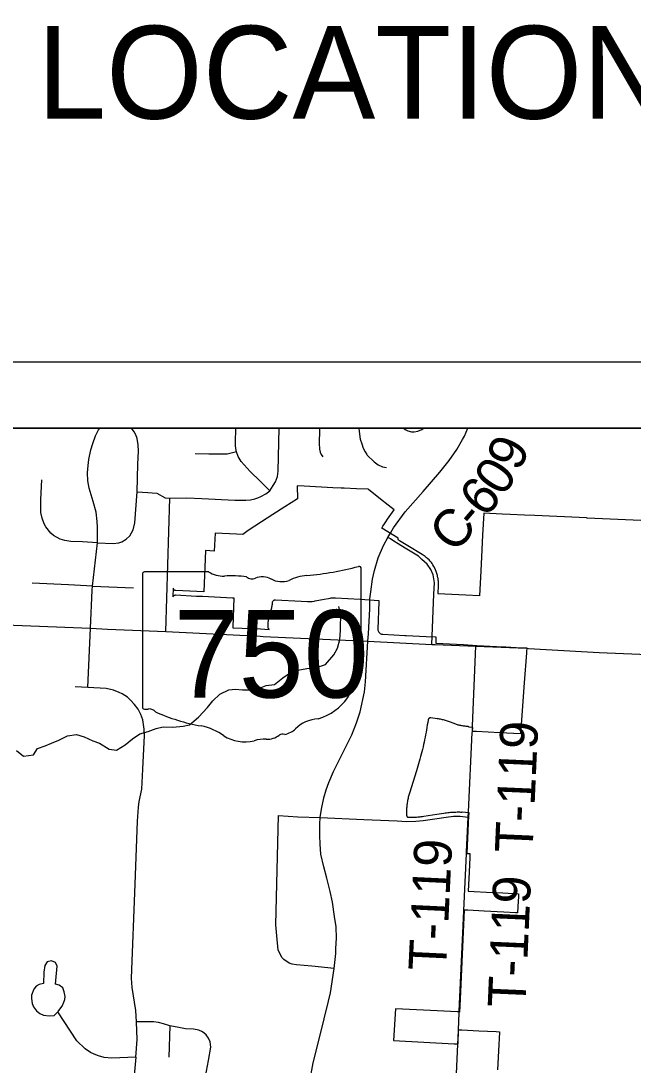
# Model space of a CAD drawing. Extents: x 0 to 34, y 0 to 22.
# Drawn here: x 14.723 to 15.645, y 9.224 to 10.798 of the extents above; entities that cross this region are included whole.
import ezdxf

# ---------------------------------------------------------------- set-up
doc = ezdxf.new("R2010")
doc.units = 0
for name, color, linetype in [('Default', 7, 'Continuous'), ('GM_X_Corporation', 7, 'Continuous'), ('GM_X_County_Road', 7, 'Continuous'), ('GM_X_County_Road_Text', 7, 'Continuous'), ('GM_X_Minor_River', 7, 'Continuous'), ('GM_X_State_Location', 7, 'Continuous'), ('GM_X_State_Route', 7, 'Continuous'), ('GM_X_State_Shield', 7, 'Continuous'), ('GM_X_Township_Road', 7, 'Continuous'), ('GM_X_Township_Road_Text', 7, 'Continuous'), ('SH_Data', 7, 'Continuous')]:
    doc.layers.add(name, color=color, linetype=linetype)

msp = doc.modelspace()

# ---------------------------------------------------------------- linework, layer by layer
at = {"layer": 'GM_X_Corporation'}
for points in [[(19.5646, 10.1841), (12.7646, 10.1841), (12.7646, 8.6719), (12.7953, 8.6676), (12.8119, 8.6756), (12.8296, 8.6783), (12.8448, 8.6761), (12.8988, 8.6726), (13.0467, 8.6615), (13.1161, 8.6564), (13.1948, 8.6507), (13.3525, 8.6386), (13.4613, 8.6292), (13.7169, 8.6042), (13.795, 8.6047), (14.2608, 8.5815), (14.4977, 8.5718), (14.6084, 8.5661), (14.9063, 8.5471), (15.334, 8.5309), (15.3473, 8.5302), (16.0546, 8.4904)], [(17.9872, 10.1841), (13.2832, 10.1841)], [(15.6572, 10.0447), (15.5762, 10.0485), (15.5753, 10.0486), (15.4974, 10.0522), (15.4819, 10.0529), (15.46, 10.054), (15.4479, 10.0545), (15.4203, 10.0559), (15.4186, 10.0226), (15.4168, 9.9902), (15.4157, 9.9689), (15.4137, 9.9314), (15.3935, 9.9322), (15.3513, 9.9341), (15.3514, 9.9349), (15.352, 9.9469), (15.3521, 9.9503), (15.3521, 9.9505), (15.352, 9.9518), (15.3519, 9.9533), (15.3518, 9.9546), (15.3515, 9.9572), (15.3513, 9.9585), (15.3508, 9.9608), (15.3505, 9.9619), (15.3501, 9.9635), (15.3497, 9.9649), (15.3487, 9.9678), (15.3477, 9.9702), (15.347, 9.972), (15.3453, 9.9752), (15.3437, 9.9778), (15.3425, 9.9797), (15.3413, 9.9812), (15.3396, 9.9834), (15.3379, 9.9853), (15.3362, 9.9871), (15.3359, 9.987), (15.3355, 9.9874), (15.3341, 9.9887), (15.3322, 9.9903), (15.3307, 9.9915), (15.329, 9.9926), (15.3274, 9.9937), (15.325, 9.9951), (15.3085, 10.005), (15.2932, 10.0142), (15.2928, 10.0145), (15.2924, 10.0149), (15.292, 10.0153), (15.2918, 10.0157), (15.2915, 10.0163), (15.2914, 10.017), (15.2913, 10.0178), (15.2913, 10.0179), (15.2914, 10.0183), (15.2666, 10.0332), (15.2682, 10.036), (15.2706, 10.0398), (15.2726, 10.0429), (15.2753, 10.0469), (15.2777, 10.0503), (15.2801, 10.0538), (15.2827, 10.0572), (15.2851, 10.0606), (15.2716, 10.0713), (15.2711, 10.0717), (15.2695, 10.073), (15.2468, 10.0915), (15.2463, 10.0919), (15.2286, 10.0926), (15.2101, 10.0933), (15.2087, 10.0934), (15.2052, 10.0935), (15.1927, 10.0942), (15.1497, 10.0965), (15.1392, 10.0971), (15.1395, 10.0774), (15.1206, 10.0654), (15.1025, 10.0537), (15.0852, 10.0425), (15.0655, 10.0298), (15.0573, 10.0238), (15.0477, 10.0243), (15.0153, 10.0258), (15.014, 9.9986), (15.0011, 9.9993), (14.9983, 9.937), (14.956, 9.939), (14.9557, 9.939), (14.9554, 9.9391), (14.9551, 9.9391), (14.9547, 9.9393), (14.9544, 9.9394), (14.9542, 9.9396), (14.9539, 9.9397), (14.9536, 9.94), (14.9534, 9.9402), (14.9532, 9.9404), (14.953, 9.9407), (14.9529, 9.941), (14.9527, 9.9413), (14.9526, 9.9416), (14.9525, 9.9419), (14.9525, 9.9422), (14.9524, 9.9426), (14.9524, 9.9429), (14.9519, 9.9298), (14.9522, 9.93), (14.9524, 9.9306), (14.9528, 9.9311), (14.953, 9.9314), (14.9535, 9.9317), (14.954, 9.9321), (14.9545, 9.9323), (14.9551, 9.9324), (14.9557, 9.9325), (14.9876, 9.9309), (14.9963, 9.9305), (15.0418, 9.9282), (15.0437, 9.9281), (15.0421, 9.8839), (15.0421, 9.883), (15.0837, 9.8812), (15.0971, 9.8806), (15.0967, 9.8809), (15.0964, 9.8812), (15.0962, 9.8815), (15.0959, 9.8819), (15.0957, 9.8822), (15.0956, 9.8826), (15.0955, 9.883), (15.0954, 9.8836), (15.0954, 9.884), (15.0956, 9.8889), (15.0958, 9.8955), (15.0959, 9.8975), (15.0962, 9.8987), (15.0966, 9.9003), (15.1008, 9.9133), (15.1011, 9.9146), (15.1014, 9.9159), (15.1016, 9.9172), (15.1017, 9.9185), (15.1018, 9.921), (15.1019, 9.9217), (15.102, 9.9221), (15.1023, 9.9228), (15.1027, 9.9234), (15.1032, 9.9239), (15.1036, 9.9242), (15.104, 9.9244), (15.1046, 9.9247), (15.1051, 9.9249), (15.1055, 9.925), (15.1062, 9.9251), (15.1453, 9.9231), (15.1548, 9.9227), (15.1566, 9.9226), (15.1592, 9.9226), (15.1619, 9.9228), (15.1646, 9.9231), (15.1663, 9.9234), (15.1797, 9.9261), (15.1864, 9.9274), (15.1887, 9.9278), (15.1902, 9.928), (15.1918, 9.9281), (15.1933, 9.9282), (15.1948, 9.9282), (15.1971, 9.9282), (15.234, 9.9264), (15.2624, 9.9243), (15.2623, 9.922), (15.2608, 9.881), (15.2608, 9.8801), (15.2608, 9.8795), (15.2611, 9.8784), (15.2615, 9.8774), (15.262, 9.8766), (15.2626, 9.8758), (15.2631, 9.8753), (15.2635, 9.8749), (15.264, 9.8746), (15.2643, 9.8744), (15.2653, 9.8738), (15.266, 9.8736), (15.2667, 9.8734), (15.2675, 9.8732), (15.268, 9.8732), (15.3012, 9.8716), (15.3033, 9.8715), (15.3334, 9.8701), (15.3483, 9.8694), (15.3483, 9.8694), (15.3483, 9.8688), (15.3481, 9.8654), (15.3479, 9.8605), (15.3479, 9.8598), (15.3897, 9.8578), (15.4099, 9.8565), (15.4497, 9.8544), (15.4534, 9.8542), (15.469, 9.8535), (15.485, 9.8528), (15.485, 9.8522), (15.4846, 9.8471), (15.4845, 9.8452), (15.4812, 9.8002), (15.4755, 9.7233), (15.4447, 9.7248), (15.4092, 9.7265), (15.4069, 9.7267), (15.4035, 9.7268), (15.4038, 9.7329), (15.3981, 9.7333), (15.3978, 9.7335), (15.3974, 9.7337), (15.397, 9.7339), (15.3966, 9.734), (15.3962, 9.7341), (15.3958, 9.7342), (15.3954, 9.7343), (15.395, 9.7343), (15.3936, 9.7344), (15.3923, 9.7345), (15.391, 9.7346), (15.3897, 9.7348), (15.3884, 9.735), (15.387, 9.7352), (15.3857, 9.7355), (15.3844, 9.7358), (15.3831, 9.7361), (15.3819, 9.7364), (15.3806, 9.7368), (15.3793, 9.7372), (15.3781, 9.7376), (15.3768, 9.7381), (15.3756, 9.7386), (15.3743, 9.7391), (15.3729, 9.7397), (15.3715, 9.7403), (15.37, 9.7408), (15.3686, 9.7413), (15.3671, 9.7418), (15.3656, 9.7423), (15.3642, 9.7428), (15.3627, 9.7432), (15.3612, 9.7436), (15.3597, 9.744), (15.3582, 9.7443), (15.3566, 9.7447), (15.355, 9.745), (15.3535, 9.7452), (15.3519, 9.7455), (15.3503, 9.7457), (15.3405, 9.747), (15.3401, 9.7471), (15.3398, 9.7471), (15.3395, 9.747), (15.3392, 9.747), (15.3389, 9.7469), (15.3386, 9.7468), (15.3383, 9.7467), (15.338, 9.7465), (15.3377, 9.7463), (15.3375, 9.7461), (15.3373, 9.7459), (15.3371, 9.7456), (15.3369, 9.7454), (15.3367, 9.7451), (15.3366, 9.7448), (15.3365, 9.7445), (15.3364, 9.7442), (15.3363, 9.7439), (15.3358, 9.7402), (15.3352, 9.7365), (15.3346, 9.7328), (15.334, 9.7291), (15.3333, 9.7254), (15.3326, 9.7217), (15.3319, 9.718), (15.3312, 9.7143), (15.3304, 9.7106), (15.3296, 9.707), (15.3288, 9.7033), (15.3279, 9.6996), (15.327, 9.696), (15.3261, 9.6924), (15.3251, 9.6887), (15.3242, 9.6851), (15.3232, 9.6815), (15.3221, 9.6779), (15.3211, 9.6743), (15.32, 9.6707), (15.3189, 9.6671), (15.3083, 9.6337), (15.3078, 9.6321), (15.3074, 9.6305), (15.3069, 9.629), (15.3065, 9.6274), (15.3062, 9.6258), (15.3058, 9.6241), (15.3055, 9.6225), (15.3052, 9.6209), (15.305, 9.6193), (15.3048, 9.6177), (15.3046, 9.616), (15.3044, 9.6144), (15.3043, 9.6128), (15.3041, 9.6111), (15.3041, 9.6095), (15.3038, 9.6019), (15.3038, 9.6015), (15.3038, 9.6006), (15.3039, 9.6002), (15.304, 9.5998), (15.3042, 9.5994), (15.3043, 9.599), (15.3045, 9.5986), (15.3047, 9.5983), (15.3049, 9.5979), (15.3052, 9.5976), (15.3059, 9.5975), (15.3067, 9.5975), (15.3077, 9.5975), (15.308, 9.5975), (15.3098, 9.5974), (15.3116, 9.5974), (15.3135, 9.5975), (15.3153, 9.5975), (15.3171, 9.5976), (15.319, 9.5977), (15.3208, 9.5978), (15.3226, 9.598), (15.3244, 9.5982), (15.3262, 9.5984), (15.3281, 9.5986), (15.3299, 9.5989), (15.3497, 9.602), (15.3602, 9.6036), (15.3622, 9.6039), (15.3641, 9.6042), (15.3661, 9.6044), (15.3681, 9.6046), (15.3701, 9.6048), (15.3721, 9.605), (15.3741, 9.6051), (15.3761, 9.6052), (15.3781, 9.6052), (15.38, 9.6053), (15.382, 9.6053), (15.3835, 9.6053), (15.385, 9.6052), (15.3866, 9.6052), (15.3871, 9.6052), (15.3875, 9.6052), (15.3878, 9.6053), (15.3976, 9.6047), (15.3969, 9.591), (15.3968, 9.5885), (15.3948, 9.5428), (15.3983, 9.5426), (15.3995, 9.5426), (15.3993, 9.5374), (15.3982, 9.5144), (15.3969, 9.4861), (15.4336, 9.4841), (15.4489, 9.4833), (15.4726, 9.482), (15.4724, 9.4781), (15.4718, 9.4629), (15.4713, 9.4534), (15.4681, 9.4535), (15.4505, 9.4544), (15.4209, 9.4559), (15.3962, 9.4572), (15.3956, 9.4572), (15.3909, 9.4574), (15.3905, 9.4466), (15.3846, 9.3233), (15.3837, 9.3037), (15.3815, 9.3038), (15.3801, 9.3039), (15.34, 9.306), (15.2873, 9.3087), (15.2844, 9.2606), (15.3758, 9.2558), (15.3779, 9.2557), (15.3817, 9.2555), (15.3824, 9.2769), (15.3875, 9.2767), (15.4127, 9.2755), (15.4388, 9.2742), (15.4438, 9.274), (15.4438, 9.2733), (15.4425, 9.245), (15.4421, 9.2357), (15.4412, 9.2168)]]:
    msp.add_lwpolyline(points, dxfattribs=at)
at = {"layer": 'GM_X_County_Road'}
for p, q in [((15.3913, 10.1717), (15.3963, 10.1841)), ((15.2488, 9.9266), (15.2502, 9.9373))]:
    msp.add_line(p, q, dxfattribs=at)
for points in [[(15.2801, 10.0267), (15.2842, 10.0336), (15.3017, 10.058), (15.329, 10.0887), (15.3539, 10.1175), (15.3684, 10.1354), (15.3799, 10.1518), (15.3885, 10.167), (15.3913, 10.1717)], [(15.2502, 9.9373), (15.2527, 9.9565), (15.2556, 9.9695), (15.261, 9.9883), (15.2694, 10.0069), (15.2756, 10.019), (15.2801, 10.0267)], [(15.2454, 9.8626), (15.2467, 9.8739), (15.2485, 9.9117), (15.2486, 9.9255), (15.2488, 9.9266)], [(15.1737, 9.5569), (15.1731, 9.5699), (15.1732, 9.587), (15.1739, 9.5969), (15.1757, 9.6094), (15.1793, 9.6264), (15.183, 9.6388), (15.1869, 9.6497), (15.1941, 9.6665), (15.2129, 9.7047), (15.2213, 9.7218), (15.2284, 9.7399), (15.2339, 9.7565), (15.2404, 9.7864), (15.2421, 9.8013), (15.2454, 9.8626)], [(15.1976, 9.3994), (15.1982, 9.4149), (15.1979, 9.4323), (15.1956, 9.4478), (15.1921, 9.4695), (15.1889, 9.4856), (15.184, 9.5053), (15.1795, 9.5224), (15.1748, 9.5418), (15.1737, 9.5569)], [(15.1864, 9.3203), (15.1895, 9.3327), (15.1948, 9.3695), (15.1972, 9.3917), (15.1976, 9.3994)], [(15.1574, 9.1952), (15.1576, 9.1972), (15.1633, 9.2272), (15.1732, 9.2668), (15.1864, 9.3203)]]:
    msp.add_lwpolyline(points, dxfattribs=at)
at = {"layer": 'GM_X_Minor_River'}
msp.add_lwpolyline([(14.7159, 9.698), (14.7265, 9.6893), (14.7416, 9.6915), (14.7477, 9.701), (14.7591, 9.7052), (14.7689, 9.7093), (14.7799, 9.7135), (14.7931, 9.72), (14.8064, 9.7222), (14.8181, 9.7184), (14.8313, 9.7124), (14.8412, 9.7089), (14.8559, 9.6998), (14.8669, 9.6983), (14.8798, 9.7067), (14.8911, 9.7154), (14.9021, 9.723), (14.9146, 9.7267), (14.9267, 9.7313), (14.9373, 9.7336), (14.9517, 9.7332), (14.9672, 9.7347), (14.977, 9.7366), (14.9903, 9.748), (15.0039, 9.7628), (15.0118, 9.773), (15.0224, 9.7829), (15.036, 9.7897), (15.0463, 9.7904), (15.0565, 9.7893), (15.0678, 9.7893), (15.0796, 9.7908), (15.0924, 9.7961), (15.1049, 9.7976), (15.1174, 9.8075), (15.1291, 9.8158), (15.1401, 9.8192), (15.1537, 9.8215), (15.167, 9.8226), (15.1817, 9.8276), (15.1942, 9.842), (15.1999, 9.8522), (15.2033, 9.8651), (15.2044, 9.8788), (15.2044, 9.8905), (15.2055, 9.9004), (15.2021, 9.9152)], dxfattribs=at)
at = {"layer": 'GM_X_State_Route'}
for p, q in [((15.088, 9.87), (15.2454, 9.8626)), ((15.2454, 9.8626), (15.3418, 9.858))]:
    msp.add_line(p, q, dxfattribs=at)
for points in [[(14.4741, 9.8907), (14.4887, 9.8946), (14.509, 9.8957), (14.5425, 9.8941), (14.583, 9.892), (14.8278, 9.8824), (14.8534, 9.8809), (14.9413, 9.8772), (15.0831, 9.8702), (15.088, 9.87)], [(15.3418, 9.858), (15.3471, 9.8579), (15.4085, 9.8553), (15.4846, 9.8522), (15.4875, 9.852)], [(15.4875, 9.852), (15.5941, 9.8457), (15.8025, 9.8371), (15.8597, 9.8344), (15.8637, 9.8342), (15.9626, 9.8287), (16.04, 9.8268), (16.0564, 9.8264), (16.1062, 9.8233)]]:
    msp.add_lwpolyline(points, dxfattribs=at)
at = {"layer": 'GM_X_State_Shield'}
for p, q in [((15.0058, 9.9673), (14.9092, 9.9673)), ((15.2356, 9.8675), (15.2356, 9.9722)), ((14.906, 9.9638), (14.906, 9.7637)), ((15.2355, 9.8676), (15.2356, 9.8675))]:
    msp.add_line(p, q, dxfattribs=at)
for centre, major_axis, start_param, end_param in [((14.9098, 9.9642), (0.00382, 0), 1.712693, 3.28349), ((15.0287, 9.9905), (0.037, 0), 4.042523, 4.731795), ((15.1182, 10.2401), (0.3495, 0), 4.814394, 5.042369), ((15.2319, 9.9726), (0.00367, 0), 6.141152, 7.989035), ((15.041, 9.8549), (0.133, 0), 1.404758, 1.657858), ((15.0712, 9.9653), (0.0107, 0), 3.836095, 5.185415), ((15.0869, 9.9421), (0.0222, 0), 0.950623, 2.079405), ((15.1156, 9.9739), (0.0267, 0), 4.081561, 5.145723), ((15.1628, 9.9061), (0.0703, 0), 1.699011, 2.107814), ((15.2347, 9.8598), (0.00568, 0), 1.883978, 3.671073), ((15.1986, 9.8466), (0.0341, 0), 5.934695, 6.695948), ((15.2317, 9.8671), (0.00393, 0), 5.05454, 6.418171), ((15.2487, 9.8237), (0.0248, 0), 2.387724, 3.262537), ((15.1378, 9.8104), (0.0874, 0), 5.101752, 6.440018), ((14.9098, 9.7633), (0.00385, 0), 3.00124, 4.508301), ((14.9104, 9.7837), (0.0294, 0), 4.665946, 4.897461), ((14.9164, 9.7521), (0.0106, 0), 0.519207, 1.627899), ((15.0502, 9.9319), (0.2524, 0), 4.195997, 4.488961), ((15.1746, 9.7075), (0.0479, 0), 1.647645, 2.488434), ((14.975, 9.6738), (0.079, 0), 0.823519, 1.323587), ((15.114, 9.7443), (0.0282, 0), 4.937069, 5.64225), ((15.0604, 9.7512), (0.0501, 0), 4.026481, 4.996735), ((15.0893, 9.682), (0.0412, 0), 1.495662, 1.94098), ((15.093, 9.7362), (0.0267, 0), 4.691044, 5.507374), ((15.1172, 9.7168), (0.00752, 0), 1.147584, 2.315152)]:
    msp.add_ellipse(centre, major_axis=major_axis, ratio=0.8, start_param=start_param, end_param=end_param, dxfattribs=at)
at = {"layer": 'GM_X_Township_Road'}
for p, q in [((14.9413, 9.8772), (14.947, 10.0786)), ((14.8305, 9.9456), (14.8927, 9.9432)), ((14.8236, 9.7928), (14.8278, 9.8824)), ((15.4035, 9.7352), (15.4085, 9.8553)), ((15.3972, 9.6053), (15.403, 9.7252)), ((15.3833, 9.3051), (15.3898, 9.4449)), ((14.9474, 9.283), (14.9458, 9.2355)), ((15.3812, 9.2548), (15.3816, 9.2651))]:
    msp.add_line(p, q, dxfattribs=at)
for points in [[(14.8305, 9.9456), (14.8383, 10.0111), (14.8381, 10.0346), (14.8375, 10.0433), (14.836, 10.0575), (14.8318, 10.0732), (14.8258, 10.0933), (14.8237, 10.1048), (14.823, 10.1167), (14.8241, 10.1279), (14.8251, 10.1369), (14.828, 10.1512), (14.831, 10.1607), (14.8353, 10.1724), (14.8399, 10.1812), (14.8416, 10.1841)], [(14.8383, 10.0111), (14.8616, 10.0101), (14.8705, 10.011), (14.8749, 10.0127), (14.8816, 10.0166), (14.8869, 10.0216), (14.8922, 10.0305), (14.8944, 10.041), (14.8979, 10.0879), (14.8989, 10.1295), (14.8998, 10.1495), (14.8996, 10.1588), (14.8979, 10.1686), (14.896, 10.174), (14.8934, 10.1783), (14.8893, 10.1841)], [(14.8979, 10.0879), (14.9142, 10.0872), (14.9208, 10.0867), (14.9278, 10.0858), (14.9404, 10.079), (14.947, 10.0786), (14.9727, 10.0788), (14.9956, 10.0779), (15.0453, 10.0755), (15.0616, 10.0752), (15.0686, 10.0758), (15.0752, 10.0773), (15.0797, 10.0788), (15.0844, 10.0808), (15.0918, 10.0851), (15.0977, 10.0895), (15.1031, 10.0975), (15.1062, 10.1031), (15.1093, 10.1109), (15.1107, 10.119), (15.1122, 10.1841)], [(15.0977, 10.0895), (15.0833, 10.1039), (15.0685, 10.1186), (15.0545, 10.1336), (15.0504, 10.1414), (15.0479, 10.1483), (15.0469, 10.1534), (15.0464, 10.1578), (15.0464, 10.1616), (15.0467, 10.1841)], [(15.1729, 10.1841), (15.1728, 10.1807), (15.1721, 10.1611), (15.1727, 10.1522), (15.1738, 10.1477), (15.1753, 10.1441), (15.178, 10.1405)], [(15.2322, 10.1841), (15.2324, 10.1787), (15.2341, 10.1676), (15.2363, 10.1605), (15.2386, 10.1538), (15.2415, 10.1482), (15.2439, 10.1442), (15.2448, 10.1431), (15.2549, 10.1332), (15.2612, 10.1286), (15.2679, 10.1259), (15.2735, 10.1246)], [(15.2992, 10.1841), (15.3021, 10.1817), (15.306, 10.1799), (15.3113, 10.1785), (15.3154, 10.1784), (15.321, 10.1796), (15.3271, 10.1817), (15.3302, 10.1841)], [(15.0479, 10.1483), (15.0337, 10.1447), (15.0265, 10.1446), (15.0176, 10.1447), (15.0061, 10.1449), (14.9854, 10.1454)], [(14.8383, 10.0111), (14.8157, 10.0126), (14.7979, 10.0131), (14.7892, 10.0146), (14.7821, 10.0165), (14.772, 10.0221), (14.768, 10.0258), (14.7604, 10.035), (14.758, 10.0395), (14.7546, 10.0483), (14.7527, 10.0566), (14.7529, 10.0766), (14.7541, 10.106)], [(15.2846, 10.0138), (15.2797, 10.0169), (15.2756, 10.019)], [(15.3271, 9.9859), (15.3217, 9.9908), (15.3117, 9.9972), (15.302, 10.0029), (15.2911, 10.0098), (15.2846, 10.0138)], [(15.3418, 9.858), (15.3452, 9.9338), (15.3459, 9.9508), (15.3438, 9.9627), (15.3403, 9.9709), (15.3349, 9.9789), (15.3271, 9.9859)], [(14.8305, 9.9456), (14.7944, 9.9479), (14.7399, 9.9502)], [(14.8278, 9.8824), (14.8302, 9.9396), (14.8305, 9.9456)], [(14.8949, 9.4967), (14.8986, 9.5913), (14.8998, 9.6126), (14.9009, 9.6212), (14.9049, 9.6396), (14.9067, 9.6696), (14.9088, 9.7208), (14.9087, 9.7302), (14.9064, 9.7442), (14.9036, 9.7522), (14.8995, 9.7601), (14.8942, 9.7675), (14.8881, 9.774), (14.8832, 9.7782), (14.8752, 9.7833), (14.871, 9.7854), (14.8622, 9.7888), (14.8513, 9.7914), (14.8236, 9.7928), (14.8046, 9.7938)], [(15.403, 9.7252), (15.4031, 9.7262), (15.4035, 9.7352)], [(15.3944, 9.5452), (15.3968, 9.5973), (15.3972, 9.6053)], [(15.1948, 9.3695), (15.1613, 9.3726), (15.1379, 9.375), (15.1314, 9.3759), (15.1269, 9.3775), (15.1188, 9.3827), (15.1164, 9.3856), (15.1106, 9.397), (15.1087, 9.4184), (15.1068, 9.4354), (15.1108, 9.5999)], [(15.1108, 9.5999), (15.14, 9.5979), (15.1739, 9.5969), (15.2396, 9.594), (15.2896, 9.5919), (15.3041, 9.5912), (15.3181, 9.5913), (15.329, 9.5923), (15.3467, 9.5951), (15.3637, 9.5977), (15.3748, 9.5988), (15.3814, 9.599), (15.3848, 9.599), (15.3968, 9.5973)], [(15.3898, 9.4449), (15.3904, 9.4568), (15.3943, 9.5422), (15.3944, 9.5452)], [(14.8961, 9.2358), (14.8979, 9.2623), (14.8972, 9.289), (14.8961, 9.3062), (14.8903, 9.3408), (14.8894, 9.3547), (14.8949, 9.4967)], [(14.8961, 9.2358), (14.8596, 9.2341), (14.848, 9.2351), (14.8396, 9.2375), (14.8332, 9.24), (14.8276, 9.2429), (14.8198, 9.2482), (14.8072, 9.2601), (14.7784, 9.3038), (14.785, 9.3127), (14.7876, 9.3184), (14.7889, 9.3224), (14.7893, 9.3273), (14.7882, 9.3343), (14.786, 9.3401), (14.7805, 9.3441), (14.7751, 9.3457), (14.7752, 9.3513), (14.7776, 9.3728), (14.7751, 9.3786), (14.7689, 9.381), (14.7623, 9.3792), (14.7589, 9.374), (14.7573, 9.3637), (14.7567, 9.3467), (14.7503, 9.3451), (14.7457, 9.3425), (14.7424, 9.338), (14.7387, 9.3292), (14.7386, 9.3239), (14.7395, 9.3164), (14.742, 9.3117), (14.7464, 9.3057), (14.7515, 9.3016), (14.757, 9.2989), (14.7655, 9.2981), (14.7727, 9.2983), (14.7776, 9.3031)], [(15.3816, 9.2651), (15.382, 9.2763), (15.3832, 9.3031), (15.3833, 9.3051)], [(14.9996, 9.1984), (15.0056, 9.2304), (15.009, 9.2509), (15.0078, 9.2589), (15.0054, 9.2644), (15.0018, 9.2693), (14.9963, 9.2739), (14.9909, 9.2766), (14.983, 9.2781), (14.9706, 9.2785), (14.961, 9.2803), (14.9474, 9.283), (14.9377, 9.2859), (14.9303, 9.2877), (14.9228, 9.2889), (14.9137, 9.2891), (14.8972, 9.289)], [(15.3745, 9.1149), (15.3787, 9.2001), (15.3812, 9.2548)], [(14.8961, 9.2358), (14.8933, 9.2082)]]:
    msp.add_lwpolyline(points, dxfattribs=at)
at = {"layer": 'SH_Data'}
for p, q in [((12.6646, 10.2841), (19.6646, 10.2841)), ((12.7646, 10.1841), (19.5646, 10.1841))]:
    msp.add_line(p, q, dxfattribs=at)

# ---------------------------------------------------------------- texts
at = {"layer": 'Default'}
msp.add_text('LOCATION 5 (FRA-270-20.79)', height=0.14, dxfattribs=at).set_placement((14.7471, 10.6505))
at = {"layer": 'GM_X_County_Road_Text'}
for s, rotation, p in [('9', 65.446, (15.4737, 10.1171)), ('0', 55.889, (15.449, 10.0791)), ('6', 49.9863, (15.4226, 10.0472)), ('C', 49.4048, (15.3767, 9.9935)), ('-', 49.5087, (15.4071, 10.029))]:
    msp.add_text(s, height=0.0568, rotation=rotation, dxfattribs=at).set_placement(p)
at = {"layer": 'GM_X_State_Location'}
for s in ['s', 'r']:
    msp.add_text(s, height=0.000189, dxfattribs=at).set_placement((15.0671, 9.8504))
msp.add_text('750', height=0.000189, rotation=0, dxfattribs=at).set_placement((15.0002, 9.8367))
at = {"layer": 'GM_X_State_Shield'}
msp.add_text('750', height=0.13184, dxfattribs=at).set_placement((14.9529, 9.7778))
at = {"layer": 'GM_X_Township_Road_Text'}
for rotation, p in [(87.4736, (15.4937, 9.5429)), (87.2643, (15.3634, 9.365)), (87.4784, (15.4829, 9.3098))]:
    msp.add_text('T-119', height=0.05682, rotation=rotation, dxfattribs=at).set_placement(p)

doc.saveas('drawing.dxf')
